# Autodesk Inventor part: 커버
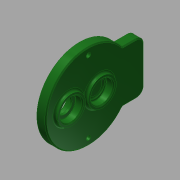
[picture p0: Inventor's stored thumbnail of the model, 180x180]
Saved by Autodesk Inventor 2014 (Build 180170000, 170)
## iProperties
Created: 2016-02
Part Number: 커버
Material: 일반
Document SubType Name: Modeling
Designer: mduedu
Density: 1 g/cm^3
Appearance: 매끄러움 - 짙은 산림 녹색
Mass: 58.0252 g
Surface Area: 178.476 cm^2
Volume: 58.0252 cm^3
Author: mduedu
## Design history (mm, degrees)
sketch "스케치1"
  geometry: C1 r 43 at (0, 0); 1 further point
  constraints: 1 centre point, 1 coincident
  dimensions: "d0" = 86 diameter of C1
extrude "돌출1" new body sketch "스케치1" distance "d1" = 9; taper "d2" = 0 deg
sketch "스케치2"
  geometry: C1 r 14 at (0, 11); 1 further point
  constraints: 1 centre point, 1 vertical alignment
  dimensions: "d3" = 28 diameter of C1; "d6" = 11 distance of C1.centre point (0, 0)
extrude "돌출2" join sketch "스케치2" distance "d7" = 3; taper "d8" = 0 deg
sketch "스케치3"
  geometry: C1 r 14 at (0, -20); 1 further point
  constraints: 1 centre point, 1 vertical alignment
  dimensions: "d9" = 28 diameter of C1; "d10" = 20 distance of C1.centre point (0, 0)
extrude "돌출3" join sketch "스케치3" distance "d11" = 3; taper "d12" = 0 deg
hole "구멍1" diameter "d15" = 22; stored, may be unused: countersink angle "d19" = 90 deg, drill point angle "d21" = 0 deg; dims "d13" = 10, "d14" = 10, "d16" = 6, "d17" = 4, "d18" = 2, "d20" = 7
hole "구멍2" diameter "d24" = 18; stored, may be unused: countersink angle "d28" = 90 deg, drill point angle "d30" = 0 deg; dims "d22" = 10, "d23" = 10, "d25" = 6, "d26" = 4, "d27" = 2, "d29" = 1
hole "구멍3" diameter "d33" = 22; stored, may be unused: countersink angle "d37" = 90 deg, drill point angle "d39" = 0 deg; dims "d34" = 6, "d35" = 4, "d36" = 2, "d38" = 7, "d73" = 10, "d74" = 10
sketch "스케치7"
  geometry: L1 (-26, 34.249)-(26, 34.249); L2 (26, 34.249)-(26, 56); L3 (26, 56)-(-26, 56); L4 (-26, 56)-(-26, 34.249); A1 r 43 centre (0, 0) between (-26, 34.249) and (26, 34.249) reference; 1 further point
  constraints: 8 end point, 2 parallel, 2 point on circle, 1 horizontal, 1 perpendicular
  dimensions: "d95" = 52 distance of L2.end L3.end; "d97" = 56 distance from line of L3 point (0, 0)
extrude "돌출5" join sketch "스케치7" stored distance "d98" = 10; taper "d99" = 0 deg
sketch "스케치4"
  geometry: C1 r 14 at (0, -20) reference; C2 r 18 at (0, -20); 1 further point
  constraints: 1 centre point, 1 coincident
  dimensions: "d40" = 36 diameter of C2
extrude "돌출4" join sketch "스케치4" distance "d41" = 4; taper "d42" = 0 deg
hole "구멍4" diameter "d45" = 22; stored, may be unused: countersink angle "d49" = 90 deg, drill point angle "d51" = 0 deg; dims "d43" = 10, "d44" = 10, "d46" = 6, "d47" = 4, "d48" = 2, "d50" = 7
hole "구멍5" diameter "d54" = 15; stored, may be unused: countersink angle "d58" = 90 deg, drill point angle "d60" = 0 deg; dims "d52" = 10, "d53" = 10, "d55" = 6, "d56" = 4, "d57" = 2, "d59" = 7
fillet "모깎기1" dims "d61" = 0.3
fillet "모깎기2" dims "d62" = 2
chamfer "모따기1" distance "d63" = 1; stored, may be unused: second distance "d64" = 2, angle "d65" = 45 deg
fillet "모깎기6" dims "d88" = 2
sketch "스케치5" dims "d67" = 72
  geometry: 4 further points
  constraints: 2 horizontal alignment, 1 coincident, 5 other
  dimensions: "d71" = 360 deg dimension on point (0, 0) point (-36, 0) (derived)
fillet "모깎기4" dims "d75" = 2
sketch "스케치6"
  geometry: 2 further points
hole "구멍6" sketch "스케치6" at (36, 0), (-36, 0) diameter "d76" = 4.5; stored, may be unused: countersink angle "d80" = 90 deg, drill point angle "d82" = 0 deg; dims "d77" = 6, "d78" = 8, "d79" = 4.6, "d81" = 8
fillet "모깎기7" dims "d100" = 8, "d101" = 2
chamfer "모따기2" distance "d90" = 1; stored, may be unused: second distance "d91" = 2, angle "d92" = 45 deg
node "솔리드1"
node "절단 모서리 투영1"
